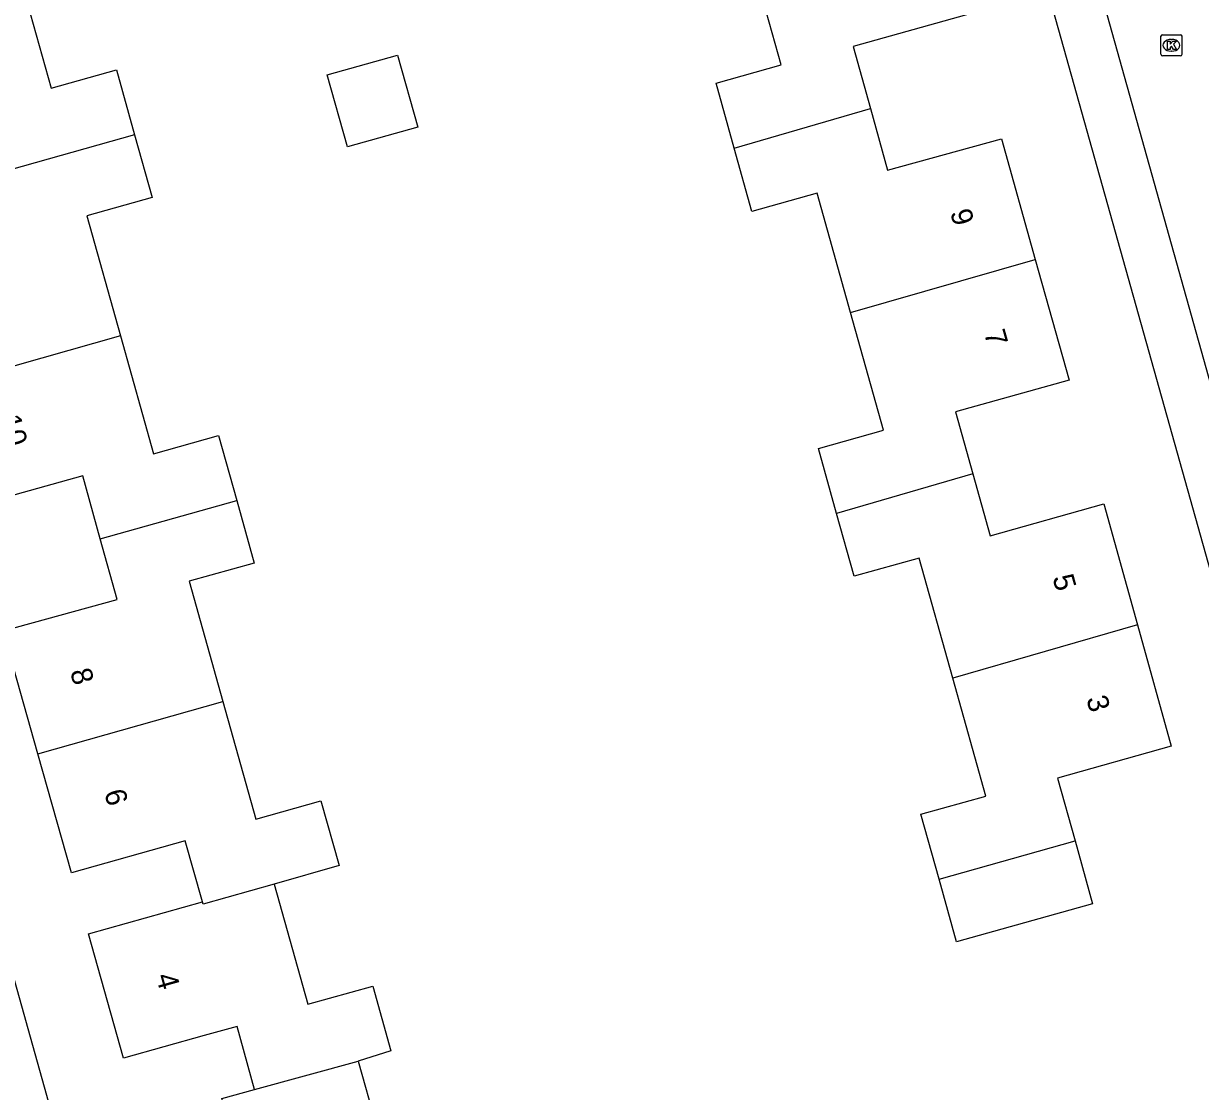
# Model space of a CAD drawing. Extents: x 159628 to 160723, y 388176 to 389416.
# Drawn here: x 160028.1 to 160083.8, y 388327.4 to 388378 of the extents above; entities that cross this region are included whole.
import ezdxf

# ---------------------------------------------------------------- set-up
doc = ezdxf.new("R2010")
doc.units = 0
for name, color, linetype in [('IMGEO_Kolk', 7, 'Continuous'), ('IMGEO_Pand', 7, 'Continuous'), ('IMGEO_Pand_nummerreeks', 7, 'Continuous'), ('IMGEO_Rijbaan_lokaal_open', 7, 'Continuous'), ('IMGEO_Voetpad_open', 7, 'Continuous')]:
    doc.layers.add(name, color=color, linetype=linetype)

msp = doc.modelspace()

# ---------------------------------------------------------------- linework, layer by layer
at = {"layer": 'IMGEO_Kolk'}
for p, q in [((160081.957, 388376.516), (160081.957, 388377.368)), ((160082.032, 388377.442), (160082.884, 388377.442)), ((160082.445, 388377.222), (160082.47, 388377.222)), ((160082.958, 388377.368), (160082.958, 388376.516)), ((160082.884, 388376.442), (160082.032, 388376.442)), ((160082.468, 388376.662), (160082.443, 388376.662))]:
    msp.add_line(p, q, dxfattribs=at)
for points in [[(160081.957, 388376.516), (160081.957, 388377.368)], [(160082.032, 388377.442), (160082.884, 388377.442)], [(160082.278, 388377.142), (160082.401, 388377.142), (160082.401, 388376.991), (160082.531, 388377.142), (160082.695, 388377.142), (160082.549, 388376.991), (160082.702, 388376.742), (160082.55, 388376.742), (160082.465, 388376.906), (160082.401, 388376.839), (160082.401, 388376.742), (160082.278, 388376.742), (160082.278, 388377.142)], [(160082.958, 388377.368), (160082.958, 388376.516)], [(160082.884, 388376.442), (160082.032, 388376.442)]]:
    msp.add_lwpolyline(points, dxfattribs=at)
for centre, start, end in [((160082.034, 388377.366), 91.552, 178.448), ((160082.034, 388377.366), 91.552, 178.448), ((160082.882, 388377.366), 1.552, 88.448), ((160082.882, 388377.366), 1.552, 88.448), ((160082.034, 388376.518), 181.552, 268.448), ((160082.034, 388376.518), 181.552, 268.448), ((160082.882, 388376.518), 271.552, 358.448), ((160082.882, 388376.518), 271.552, 358.448)]:
    msp.add_arc(centre, 0.0765, start, end, dxfattribs=at)
for centre, major_axis, ratio, start_param, end_param in [((160082.444, 388376.942), (-0.387, 0.002), 0.722429, 4.712389, 7.853982), ((160082.469, 388376.942), (-0.39, 0.002), 0.717154, 1.570796, 4.712389)]:
    msp.add_ellipse(centre, major_axis=major_axis, ratio=ratio, start_param=start_param, end_param=end_param, dxfattribs=at)
at = {"layer": 'IMGEO_Pand'}
for points in [[(160071.15, 388384.1), (160072.752, 388378.379), (160067.38, 388376.878), (160068.197, 388373.952)], [(160061.749, 388372.073), (160060.886, 388375.152), (160063.97, 388376.017), (160062.406, 388381.596)], [(160027.833, 388380.49), (160029.394, 388374.912), (160032.487, 388375.778), (160033.348, 388372.703)], [(160043.431, 388372.133), (160042.475, 388375.547), (160045.803, 388376.478), (160046.759, 388373.064), (160043.431, 388372.133)], [(160061.749, 388372.073), (160068.197, 388373.952)], [(160068.197, 388373.952), (160069.013, 388371.027), (160074.401, 388372.515), (160076.004, 388366.8)], [(160033.348, 388372.703), (160026.884, 388370.881)], [(160033.348, 388372.703), (160034.18, 388369.73), (160031.089, 388368.866), (160032.682, 388363.173)], [(160067.258, 388364.278), (160065.672, 388369.937), (160062.589, 388369.073), (160061.749, 388372.073)], [(160067.258, 388364.278), (160076.004, 388366.8)], [(160076.004, 388366.8), (160077.607, 388361.084), (160072.223, 388359.574), (160073.044, 388356.642)], [(160066.601, 388354.755), (160065.737, 388357.839), (160068.821, 388358.703), (160067.258, 388364.278)], [(160032.682, 388363.173), (160023.929, 388360.706)], [(160032.682, 388363.173), (160034.245, 388357.589), (160037.327, 388358.452), (160038.186, 388355.383)], [(160031.721, 388353.561), (160030.891, 388356.542), (160025.516, 388355.045), (160023.929, 388360.706)], [(160073.044, 388356.642), (160066.601, 388354.755)], [(160073.044, 388356.642), (160073.866, 388353.709), (160079.249, 388355.218), (160080.85, 388349.482)], [(160031.721, 388353.561), (160038.186, 388355.383)], [(160038.186, 388355.383), (160039.017, 388352.414), (160035.937, 388351.553), (160037.532, 388345.856)], [(160072.11, 388346.96), (160070.515, 388352.652), (160067.432, 388351.788), (160066.601, 388354.755)], [(160028.764, 388343.385), (160027.125, 388349.2), (160032.519, 388350.696), (160031.721, 388353.561)], [(160080.85, 388349.482), (160072.11, 388346.96)], [(160080.85, 388349.482), (160082.451, 388343.744), (160077.057, 388342.232), (160077.892, 388339.255)], [(160071.453, 388337.433), (160070.59, 388340.514), (160073.673, 388341.379), (160072.11, 388346.96)], [(160028.764, 388343.385), (160037.532, 388345.856)], [(160037.532, 388345.856), (160039.091, 388340.285), (160042.173, 388341.148), (160043.03, 388338.086), (160039.958, 388337.198)], [(160036.559, 388336.367), (160035.746, 388339.256), (160030.355, 388337.738), (160028.764, 388343.385)], [(160077.892, 388339.255), (160078.726, 388336.279), (160072.282, 388334.473), (160071.453, 388337.433)], [(160071.453, 388337.433), (160077.892, 388339.255)], [(160039.958, 388337.198), (160036.592, 388336.25), (160036.559, 388336.367)], [(160039.958, 388337.198), (160041.549, 388331.515), (160044.631, 388332.378), (160045.491, 388329.306), (160043.934, 388328.825)], [(160039.034, 388327.478), (160038.199, 388330.462), (160036.646, 388330.028), (160032.82, 388328.959), (160031.167, 388334.848), (160036.559, 388336.367)], [(160043.934, 388328.825), (160044.769, 388325.844), (160038.317, 388324.038), (160037.477, 388327.05), (160039.034, 388327.478)], [(160039.034, 388327.478), (160043.934, 388328.825)]]:
    msp.add_lwpolyline(points, dxfattribs=at)
at = {"layer": 'IMGEO_Rijbaan_lokaal_open'}
msp.add_lwpolyline([(160095.449, 388321.154), (160076.62, 388388.378), (160139.18, 388405.917), (160146.522, 388407.997)], dxfattribs=at)
at = {"layer": 'IMGEO_Voetpad_open'}
for points in [[(160093.373, 388319.695), (160091.694, 388325.686), (160087.996, 388338.877), (160074.295, 388387.755), (160070.165, 388402.519)], [(160012.651, 388386.243), (160030.665, 388321.896), (160031.671, 388318.304), (160034.012, 388311.518), (160036.849, 388303.296)]]:
    msp.add_lwpolyline(points, dxfattribs=at)

# ---------------------------------------------------------------- texts
at = {"layer": 'IMGEO_Pand_nummerreeks'}
for s, rotation, p in [('9', 285.667, (160071.969, 388369.036)), ('7', 285.667, (160073.572, 388363.321)), ('10', 285.6632, (160026.942, 388359.296)), ('5', 285.5926, (160076.816, 388351.733)), ('8', 285.7379, (160030.284, 388347.279)), ('3', 285.5926, (160078.417, 388345.996)), ('6', 285.7379, (160031.898, 388341.552)), ('4', 285.6791, (160034.345, 388332.849))]:
    msp.add_text(s, height=1, rotation=rotation, dxfattribs=at).set_placement(p)

doc.saveas('drawing.dxf')
